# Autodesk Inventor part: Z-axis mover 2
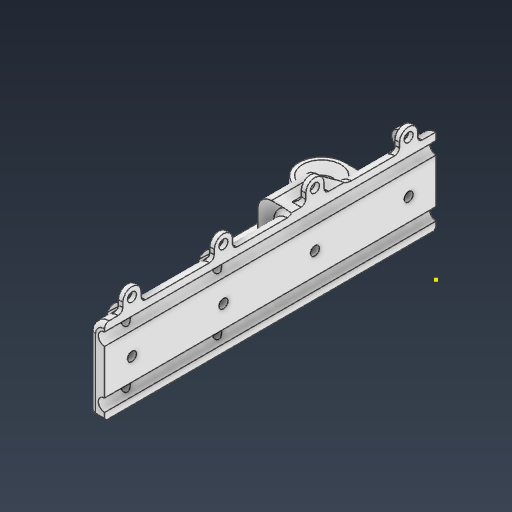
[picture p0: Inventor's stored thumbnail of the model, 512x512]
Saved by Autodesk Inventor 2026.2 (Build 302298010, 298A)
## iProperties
Created: 2026-04
Part Number: Z-axis mover 2
Material: ABS 플라스틱
Document SubType Name: Modeling
Designer: work
Density: 1.06 g/cm^3
Appearance: 매끄러움 - 흰색
Mass: 54.2435 g
Surface Area: 203.358 cm^2
Volume: 51.1731 cm^3
Author: work
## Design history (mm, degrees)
sketch "스케치1"
  geometry: L1 (0, 0)-(8, 0); L2 (0, 0)-(0, 8); L3 (0, 0)-(-8, 0); L4 (0, 0)-(0, -8); L5 (0, 0)-(50, 0); L6 (0, 0)-(-50, 0); L7 (0, 0)-(0, 50); L8 (25, 0)-(25, -380); L9 (-25, 0)-(-25, -380); L10 (-25, 0)-(-25, 70); L11 (25, -380)-(-25, -380); L12 (25, 0)-(25, 0); L13 (25, 0)-(25, 120); L14 (-37.5, -395)-(37.5, -395); L15 (37.5, -395)-(37.5, -365); L16 (37.5, -365)-(-37.5, -365); L17 (-37.5, -365)-(-37.5, -395); L18 (-37.5, -395)-(37.5, -365); L19 (37.5, -395)-(-37.5, -365); L20 (-62.5, 38)-(62.5, 38); L21 (62.5, 38)-(62.5, -38); L22 (62.5, -38)-(-62.5, -38); L23 (-62.5, -38)-(-62.5, 38); L24 (-62.5, 38)-(62.5, -38); L25 (62.5, 38)-(-62.5, -38); L26 (62.5, -25)-(-62.5, -25); L27 (17, 38)-(-17, 38); L28 (-17, 38)-(-17, 61); L29 (-17, 61)-(17, 61); L30 (17, 61)-(17, 38); L31 (-22, 60.236)-(-22, 100); L32 (-22, 100)-(-28, 100); L33 (-28, 100)-(-28, -380); L34 (-28, -380)-(-22, -380); L35 (-22, -380)-(-22, 100); L36 (-40, 38)-(40, 38); L37 (40, 38)-(40, 18); L38 (40, 18)-(-40, 18); L39 (-40, 18)-(-40, 38); C1 r 5.25 at (0, 0); C2 r 11.3 at (0, 0); C3 r 2 at (8, 0); C4 r 2 at (0, 8); C5 r 2 at (-8, 0); C6 r 2 at (0, -8); C7 r 4.4 at (50, 0); C8 r 4.4 at (-50, 0); C9 r 4 at (0, 50); 7 further points
  constraints: 78 end point, 12 midpoint, 10 parallel, 9 centre point, 9 coincident, 8 horizontal, 6 perpendicular, 6 point on line, 5 vertical, 2 symmetric about line, 1 collinear, 22 other
  dimensions: "d0" = 10.5 diameter of C1; "d1" = 22.6 diameter of C2; "d2" = 8 distance of L1.start L1.end; "d3" = 4 diameter of C3; "d6" = 360 deg dimension on C1.centre L1.end (derived); "d8" = 50 distance of L4.start L5.end; "d9" = 8.8 diameter of C7; "d10" = 50 distance of L4.start L7.end; "d11" = 8 diameter of C9; "d12" = 12 distance of point (0, 38) L7.end; "d15" = 450 distance of L9.end L10.end; "d16" = 25 distance from line of point (0, 0) L8; "d17" = 25 distance from line of L10 C1.centre; "d19" = 500 distance of L8.end L13.end; "d20" = 120 vertical distance of point (0, 0) L13.end; "d21" = 75 distance between parallel lines of L17 L15; "d22" = 30 distance of L14.end L15.end; "d23" = 125 distance between parallel lines of L23 L21; "d24" = 25 distance from line of point (0, 0) L26; "d25" = 340 distance between parallel lines of L16 L26 (derived); "d26" = 34 distance of L28.end L29.end; "d27" = 23 distance of L27.end L28.end; "d30" = 6 distance between parallel lines of L33 L35; "d31" = 80 distance of L37.end L38.end; "d32" = 20 distance of L36.end L37.end; "d60" = 30 distance of L10.end point (-25, 100)
  node "스케치 - 원형 패턴1" dims "d6" = 360 deg (derived)
extrude "돌출1" new body sketch "스케치1" distance "d33" = 6; taper "d34" = 0 deg
extrude "돌출2" join sketch "스케치1" distance "d35" = 4; taper "d36" = 0 deg
extrude "돌출3" join sketch "스케치1" distance "d37" = 38; taper "d38" = 0 deg
sketch "스케치2"
  geometry: L1 (102.5, 6)-(22.5, 6) reference; L2 (87.5, 6)-(87.5, 31); L3 (93.5, 6)-(93.5, 31); L4 (81.5, 31)-(81.5, 6); L5 (0, 0)-(125, 0) reference; L6 (62.5, 6)-(37.5, 6); L7 (37.5, 6)-(37.5, 31); L8 (37.5, 31)-(62.5, 31); L9 (62.5, 31)-(62.5, 6); L10 (30.5, 4)-(44.5, 4); L11 (44.5, 4)-(44.5, 18); L12 (44.5, 18)-(30.5, 18); L13 (30.5, 18)-(30.5, 4); L14 (30.5, 4)-(44.5, 18); L15 (44.5, 4)-(30.5, 18); L16 (44.5, -10.5)-(86.5, -10.5); L17 (86.5, -10.5)-(86.5, 32.5); L18 (86.5, 32.5)-(44.5, 32.5); L19 (44.5, 32.5)-(44.5, -10.5); L20 (44.5, -10.5)-(86.5, 32.5); L21 (86.5, -10.5)-(44.5, 32.5); L22 (47.5, 32.5)-(47.5, -10.5); L23 (37.5, 6)-(37.5, 31); L24 (43.5, 6)-(43.5, 31); L25 (31.5, 31)-(31.5, 6); L26 (47, 1.5)-(28, 1.5); L27 (28, 1.5)-(28, 20.5); L28 (28, 20.5)-(47, 20.5); L29 (47, 20.5)-(47, 1.5); L30 (47, 1.5)-(28, 20.5); L31 (28, 1.5)-(47, 20.5); C1 r 2.75 at (87.5, 6); C2 r 2.75 at (87.5, 31); C3 r 4.25 at (37.5, 31); A1 r 6 centre (87.5, 6) between (81.5, 6) and (93.5, 6); A2 r 6 centre (87.5, 31) between (93.5, 31) and (81.5, 31); A3 r 6 centre (37.5, 6) between (31.5, 6) and (43.5, 6); A4 r 6 centre (37.5, 31) between (43.5, 31) and (31.5, 31); 16 further points
  constraints: 62 end point, 11 midpoint, 10 parallel, 10 tangent, 8 point on circle, 7 centre point, 7 perpendicular, 5 point on line, 4 horizontal, 2 coincident
  dimensions: "d39" = 5.5 diameter of C1; "d40" = 25 distance of L2.start L6.start; "d41" = 25 distance of L2.start L2.end; "d42" = 5.5 diameter of C2; "d43" = 25 distance of L7.end L8.end; "d44" = 25 distance of L6.end L7.end; "d45" = 8.5 diameter of C3; "d46" = 14 distance of L11.end L12.end; "d47" = 14 distance of L10.end L11.end; "d48" = 43 distance of L16.end L17.end; "d50" = 20 distance of L7.end point (37.5, 11); "d51" = 39 distance between parallel lines of L17 L22; "d52" = 3 distance between parallel lines of L22 L19; "d59" = 2.5 distance between parallel lines of L28 L12
extrude "돌출4" join sketch "스케치2" distance "d53" = 145; taper "d54" = 0 deg
extrude "돌출5" cut sketch "스케치2" extent not by distance; stored distance "d55" = 10; taper "d56" = 0 deg
sketch "스케치3"
  geometry: L1 (-31.5, 20.5)-(-31.5, 31) reference; L2 (-43.5, 31)-(-43.5, 20.5) reference; L3 (-30.5, 4)-(-44.5, 4) reference; L4 (-44.5, 18)-(-30.5, 18) reference; L5 (-28, 20.5)-(-31.5, 20.5) reference; L6 (-43.5, 20.5)-(-47, 20.5) reference; L7 (-47, 1.5)-(-41.469, 1.5) reference; L8 (-33.531, 1.5)-(-28, 1.5) reference; L9 (-28, 1.5)-(-28, 20.5) reference; L10 (-30.5, 18)-(-30.5, 4) reference; L11 (-44.5, 4)-(-44.5, 18) reference; L12 (-47, 20.5)-(-47, 1.5) reference; C1 r 6 at (-37.5, 31); A1 r 6 centre (-37.5, 6) between (-41.469, 1.5) and (-33.531, 1.5) reference; A2 r 6 centre (-37.5, 31) between (-31.5, 31) and (-43.5, 31) reference; 5 further points
  constraints: 1 centre point, 1 concentric
extrude "돌출6" cut sketch "스케치3" stored distance "d57" = 145; taper "d58" = 0 deg
sketch "스케치5"
  geometry: L1 (29.25, 38)-(20.75, 38) reference; L2 (18, 38)-(32, 38) reference; L3 (32, 38)-(18, 38) reference; L4 (-25, 38)-(62.5, 38) reference; L5 (40, 38)-(62.5, 38) reference; L6 (-40, 38)-(40, 38) reference; L7 (-62.5, 38)-(-40, 38) reference; L8 (-62.5, 38)-(-25, 38) reference; L9 (-25, 38)-(-31, 38) reference; L10 (-31, 38)-(-19, 38) reference; L11 (-19, 38)-(-25, 38) reference; L12 (25, 38)-(25, 88); L13 (9.5, 103.5)-(40.5, 103.5); L14 (40.5, 103.5)-(40.5, 72.5); L15 (40.5, 72.5)-(9.5, 72.5); L16 (9.5, 72.5)-(9.5, 103.5); L17 (9.5, 103.5)-(40.5, 72.5); L18 (40.5, 103.5)-(9.5, 72.5); L19 (1.5, 111.5)-(48.5, 111.5); L20 (48.5, 111.5)-(48.5, 64.5); L21 (48.5, 64.5)-(1.5, 64.5); L22 (1.5, 64.5)-(1.5, 111.5); L23 (1.5, 111.5)-(48.5, 64.5); L24 (48.5, 111.5)-(1.5, 64.5); L25 (-22.25, 120)-(-22.25, -25) reference; L26 (-31, 38)-(-19, 38) reference; L27 (-31, 38)-(-31, 120) reference; L28 (-19, 120)-(-31, 120) reference; L29 (-19, 38)-(-19, 120) reference; L30 (62.5, 38)-(62.5, -25) reference; L31 (40, 18)-(40, 38) reference; L32 (-62.5, 38)-(-25, 38) reference; L33 (-62.5, -25)-(-62.5, 38) reference; L34 (62.5, -25)-(-62.5, -25) reference; L35 (62.5, 38)-(62.5, -25) reference; L36 (-25, 38)-(62.5, 38) reference; L37 (-19, 38)-(19, 38); L38 (19, 38)-(19, 62); L39 (19, 62)-(-19, 62); L40 (-19, 62)-(-19, 38); L41 (-19, 38)-(-19, 120) reference; C1 r 12.5 at (25, 88); C2 r 2 at (9.5, 72.5); C3 r 2 at (40.5, 103.5); C4 r 2 at (9.5, 103.5); C5 r 2 at (40.5, 72.5); C6 r 2 at (0, -8) reference; C7 r 2 at (8, 0) reference; C8 r 2 at (0, 8) reference; C9 r 2 at (-8, 0) reference; C10 r 5.25 at (0, 0) reference; C11 r 4.4 at (50, 0) reference; C12 r 4.4 at (-50, 0) reference; A1 r 28.971 centre (1.5, 140.471) between (-19, 120) and (1.5, 111.5); A2 r 15 centre (63.5, 64.5) between (48.5, 64.5) and (55.046, 52.109); A3 r 17.08 centre (45.42, 38) between (62.5, 38) and (55.046, 52.109); 15 further points
  constraints: 34 end point, 8 centre point, 6 parallel, 6 point on circle, 5 coincident, 5 midpoint, 4 perpendicular, 4 tangent, 3 horizontal, 2 point on line, 5 other
  dimensions: "d61" = 25 distance from line of point (0, 38) L12; "d62" = 25 diameter of C1; "d63" = 31 distance of L14.end L15.end; "d64" = 31 distance of L13.end L14.end; "d65" = 4 diameter of C2; "d66" = 4 diameter of C3; "d67" = 4 diameter of C4; "d68" = 4 diameter of C5; "d69" = 50 distance of L12.start L12.end; "d70" = 8 distance between parallel lines of L14 L20; "d71" = 15 radius of A2; "d73" = 24 distance of L39.end L37.start
extrude "돌출7" join sketch "스케치5" distance "d74" = 6; taper "d75" = 0 deg
sketch "스케치6"
  geometry: L1 (-81.5, 31)-(-81.5, 0) reference; L2 (-81.5, 0)-(-43.5, 0) reference; L3 (-43.5, 0)-(-43.5, 4) reference; L4 (-30.5, 6)-(-22.5, 6) reference; L5 (-44.5, 18)-(-44.5, 4) reference; L6 (-30.5, 18)-(-44.5, 18) reference; L7 (-30.5, 6)-(-30.5, 18) reference; L8 (-22.5, 6)-(-22.5, 38) reference; L9 (-102.5, 38)-(-22.5, 38) reference; L10 (-102.5, 6)-(-102.5, 38) reference; L11 (-125, 6)-(-102.5, 6) reference; L12 (-125, 0)-(-125, 6) reference; L13 (-125, 0)-(-93.5, 0) reference; L14 (-93.5, 0)-(-93.5, 31) reference; L15 (-81.5, 6)-(-81.5, 31) reference; L16 (-93.5, 31)-(-93.5, 0) reference; L17 (0, 0)-(-125, 0) reference; L18 (-93.5, 6)-(-81.5, 6); L19 (-81.5, 6)-(-81.5, 0); L20 (-81.5, 0)-(-93.5, 0); L21 (-93.5, 0)-(-93.5, 6); L22 (-81.5, 0)-(-93.5, 0) reference; L23 (-81.5, 0)-(-81.5, 6) reference; L24 (-90.25, 6)-(-84.75, 6) reference; L25 (-44.5, 4)-(-43.5, 4) reference; C1 r 4.25 at (-37.5, 31) reference; C2 r 2.75 at (-87.5, 31) reference; A1 r 6 centre (-87.5, 31) between (-81.5, 31) and (-93.5, 31) reference; A2 r 6 centre (-87.5, 31) between (-81.5, 31) and (-93.5, 31) reference; A3 r 2.75 centre (-87.5, 6) between (-84.75, 6) and (-90.25, 6) reference; 10 further points
  constraints: 8 end point, 2 parallel, 2 point on line, 1 horizontal, 1 perpendicular
extrude "돌출8" join sketch "스케치6" stored distance "d76" = 6; taper "d77" = 0 deg
sketch "스케치7"
  geometry: L1 (47, 6)-(81.5, 6) reference; L2 (47, 20.5)-(43.5, 20.5) reference; L3 (43.5, 20.5)-(43.5, 31) reference; L4 (31.5, 31)-(31.5, 20.5) reference; L5 (31.5, 20.5)-(28, 20.5) reference; L6 (28, 20.5)-(28, 6) reference; L7 (0, 6)-(28, 6) reference; L8 (0, 0)-(0, 6) reference; L9 (0, 0)-(125, 0) reference; L10 (125, 0)-(125, 6) reference; L11 (93.5, 6)-(125, 6) reference; L12 (93.5, 6)-(93.5, 31) reference; L13 (81.5, 31)-(81.5, 6) reference; L14 (44.5, 18)-(44.5, 4) reference; L15 (44.5, 4)-(30.5, 4) reference; L16 (30.5, 4)-(30.5, 18) reference; L17 (30.5, 18)-(44.5, 18) reference; L18 (43.5, 4)-(30.5, 4) reference; L19 (43.5, 4)-(43.5, 6) reference; L20 (30.5, 6)-(43.5, 6) reference; L21 (30.5, 4)-(30.5, 6) reference; L22 (81.5, 0)-(43.5, 0) reference; L23 (81.5, 0)-(81.5, 6) reference; L24 (43.5, 6)-(81.5, 6) reference; L25 (43.5, 0)-(43.5, 6) reference; L26 (47, 6)-(47, 20.5) reference; C1 r 2.75 at (87.5, 31) reference; C2 r 2.75 at (87.5, 6) reference; C3 r 2.75 at (87.5, 31) reference; A1 r 6 centre (37.5, 31) between (43.5, 31) and (31.5, 31) reference; A2 r 6 centre (87.5, 31) between (93.5, 31) and (81.5, 31) reference; 4 further points
extrude "돌출9" cut sketch "스케치7" extent not by distance; stored distance "d78" = 0; taper "d79" = 0 deg
sketch "스케치8"
  geometry: L1 (50.5, 10)-(74.5, 10); L2 (74.5, 10)-(74.5, 28); L3 (74.5, 28)-(50.5, 28); L4 (50.5, 28)-(50.5, 10); L5 (50.5, 10)-(74.5, 28); L6 (74.5, 10)-(50.5, 28); L7 (102.5, 38)-(22.5, 38) reference; L8 (62.5, 38)-(62.5, 0); C1 r 2 at (50.5, 28); C2 r 2 at (50.5, 10); C3 r 2 at (74.5, 10); C4 r 2 at (74.5, 28); 1 further point
  constraints: 14 end point, 4 centre point, 4 coincident, 4 midpoint, 2 parallel, 1 horizontal, 1 perpendicular, 1 vertical
  dimensions: "d80" = 24 distance of L3.end L2.end; "d81" = 18 distance of L2.end L1.end; "d82" = 4 diameter of C1; "d83" = 4 diameter of C2; "d84" = 4 diameter of C3; "d85" = 4 diameter of C4
extrude "돌출10" cut sketch "스케치8" extent not by distance; stored distance "d86" = 18 (derived); taper "d87" = 0 deg
sketch "스케치9"
  geometry: L1 (59, -32)-(59, -7) reference; L2 (71, -7)-(71, -32) reference; L3 (80, -32)-(71, -32) reference; L4 (80, -32)-(80, 0) reference; L5 (0, 0)-(80, 0) reference; L6 (0, -32)-(0, 0) reference; L7 (5.5, -32)-(0, -32) reference; L8 (5.5, -32)-(5.5, -17.5) reference; L9 (5.5, -17.5)-(9, -17.5) reference; L10 (9, -17.5)-(9, -7) reference; L11 (21, -7)-(21, -17.5) reference; L12 (21, -17.5)-(24.5, -17.5) reference; L13 (59, -32)-(24.5, -32) reference; L14 (24.5, -17.5)-(24.5, -32) reference; C1 r 2 at (28, -28) reference; C2 r 2 at (52, -28) reference; C3 r 2 at (28, -10) reference; C4 r 2 at (52, -10) reference; C5 r 2 at (52, -28) reference; A1 r 6 centre (65, -7) between (71, -7) and (59, -7) reference; A2 r 6 centre (15, -7) between (21, -7) and (9, -7) reference; 5 further points
  constraints: 4 coincident
hole "구멍1" sketch "스케치9" at (52, -10), (28, -10), (28, -28), (52, -28) diameter "d88" = 4; stored, may be unused: countersink angle "d92" = 90 deg, drill point angle "d94" = 0 deg; dims "d89" = 6, "d90" = 6.2, "d91" = 4, "d93" = 8
sketch "스케치10"
  geometry: L1 (32, -98.356)-(32, -111.5) reference; L2 (32, -111.5)-(48.5, -111.5) reference; L3 (48.5, -111.5)-(48.5, -64.5) reference; L4 (62.5, -38)-(62.5, 25) reference; L5 (62.5, 25)-(34.5, 25) reference; L6 (34.5, 25)-(34.5, -18) reference; L7 (34.5, -18)-(40, -18) reference; L8 (40, -18)-(40, -38) reference; L9 (32, -38)-(40, -38) reference; L10 (32, -38)-(32, -77.644) reference; L11 (-31, -18)-(-31, 25) reference; L12 (-31, 25)-(-62.5, 25) reference; L13 (-62.5, 25)-(-62.5, -38) reference; L14 (-62.5, -38)-(-40, -38) reference; L15 (-40, -38)-(-40, -18) reference; L16 (-40, -18)-(-31, -18) reference; L17 (-50, -10)-(-31, -10); L18 (-50, 10)-(-31, 10); L19 (50, 10)-(34.5, 10); L20 (50, -10)-(34.5, -10); C1 r 4.4 at (50, 0) reference; C2 r 2 at (40.5, -72.5) reference; C3 r 2 at (40.5, -103.5) reference; C4 r 4.4 at (-50, 0) reference; A1 r 15 centre (63.5, -64.5) between (55.046, -52.109) and (48.5, -64.5) reference; A2 r 17.08 centre (45.42, -38) between (55.046, -52.109) and (62.5, -38) reference; A3 r 12.5 centre (25, -88) between (32, -98.356) and (32, -77.644) reference; A4 r 10 centre (-50, 0) between (-50, -10) and (-50, 10); A5 r 10 centre (50, 0) between (50, 10) and (50, -10); 1 further point
  constraints: 8 end point, 4 perpendicular, 4 point on circle, 4 point on line, 4 tangent, 2 centre point, 2 coincident
  dimensions: "d95" = 20 diameter of A4; "d96" = 20 diameter of A5
extrude "돌출11" join sketch "스케치10" stored distance "d97" = 10; taper "d98" = 0 deg
fillet "모깎기1" dims "d99" = 6
sketch "스케치11"
  geometry: C1 r 4.25 at (0, 0) reference; 1 further point
extrude "돌출12" cut sketch "스케치11" extent not by distance; stored distance "d100" = 0; taper "d101" = 0 deg
fillet "모깎기2" dims "d102" = 2
fillet "모깎기3" dims "d103" = 0.5
chamfer "모따기1" distance "d104" = 1; stored, may be unused: second distance "d105" = 2, angle "d106" = 45 deg
sketch "스케치12"
  geometry: L1 (17.5, -61.936)-(17.5, -78) reference; L2 (17, -62)-(-17, -62) reference; L3 (-19, -60)-(-19, -118) reference; L4 (-21, -120)-(-19.813, -120) reference; L5 (1.5, -111.5)-(17.5, -111.5) reference; L6 (17.5, -98)-(17.5, -111.5) reference; L7 (42, -40)-(42, -17.621) reference; L8 (32.5, -78)-(32.5, -40) reference; L9 (32.5, -111.5)-(32.5, -98) reference; L10 (32.5, -111.5)-(42.5, -111.5) reference; L11 (48.5, -105.5)-(48.5, -64.5) reference; L12 (62.5, -38)-(62.5, 19) reference; L13 (56.5, 25)-(36.5, 25) reference; L14 (36.5, 16)-(36.5, 25) reference; L15 (50, 12)-(40.5, 12) reference; L16 (45.657, -12)-(50, -12) reference; L17 (42, -40)-(42, -17.621) reference; L18 (32.5, -40)-(42, -40) reference; C1 r 2 at (9.5, -72.5) reference; C2 r 2 at (9.5, -103.5) reference; C3 r 2 at (40.5, -103.5) reference; C4 r 2 at (40.5, -72.5) reference; C5 r 2 at (40.5, -103.5) reference; A1 r 2 centre (17, -60) between (17, -62) and (17.5, -61.936) reference; A2 r 2 centre (-17, -60) between (-19, -60) and (-17, -62) reference; A3 r 2 centre (-21, -118) between (-21, -120) and (-19, -118) reference; A4 r 2 centre (-19.813, -118) between (-19.813, -120) and (-18.437, -119.451) reference; A5 r 28.971 centre (1.5, -140.471) between (1.5, -111.5) and (-18.437, -119.451) reference; A6 r 12.5 centre (25, -88) between (17.5, -78) and (17.5, -98) reference; A7 r 12.5 centre (25, -88) between (32.5, -98) and (32.5, -78) reference; A8 r 6 centre (42.5, -105.5) between (42.5, -111.5) and (48.5, -105.5) reference; A9 r 15 centre (63.5, -64.5) between (55.046, -52.109) and (48.5, -64.5) reference; A10 r 17.08 centre (45.42, -38) between (55.046, -52.109) and (62.5, -38) reference; A11 r 6 centre (56.5, 19) between (62.5, 19) and (56.5, 25) reference; A12 r 4 centre (40.5, 16) between (36.5, 16) and (40.5, 12) reference; A13 r 12 centre (50, 0) between (50, -12) and (50, 12) reference; A14 r 4 centre (45.657, -16) between (45.657, -12) and (42, -17.621) reference; 5 further points
  constraints: 4 coincident
hole "구멍2" sketch "스케치12" at (9.5, -103.5), (40.5, -103.5), (40.5, -72.5), (9.5, -72.5) diameter "d107" = 4; stored, may be unused: countersink angle "d111" = 90 deg, drill point angle "d113" = 0 deg; dims "d108" = 6, "d109" = 6.2, "d110" = 4, "d112" = 8
fillet "모깎기4" dims "d114" = 10
sketch "스케치13"
  geometry: L1 (78, -30)-(0, -30) reference; L2 (78, 0)-(78, -30) reference; L3 (0, 0)-(78, 0) reference; L4 (0, -30)-(0, 0) reference; L5 (68, 0)-(28, 0); L6 (28, 0)-(28, -25); L7 (28, -25)-(68, -25); L8 (68, -25)-(68, 0); C1 r 4 at (28, 0); C2 r 4 at (28, -25); C3 r 4 at (68, -25); C4 r 4 at (68, 0); 1 further point
  constraints: 8 end point, 4 centre point, 2 parallel, 1 coincident, 1 horizontal, 1 perpendicular, 1 point on line
  dimensions: "d115" = 40 distance of L7.end L6.end; "d116" = 25 distance of L6.end L5.end; "d117" = 10 distance between parallel lines of L2 L8; "d118" = 8 diameter of C1; "d119" = 8 diameter of C2; "d120" = 8 diameter of C3; "d121" = 8 diameter of C4
  node "투영된 루프17"
extrude "돌출13" join sketch "스케치13" stored distance "d122" = 8 (derived); taper "d123" = 0 deg
extrude "돌출14" join sketch "스케치13" distance "d124" = 1.5; taper "d125" = 0 deg
sketch "스케치14"
  geometry: L1 (4, 0)-(36, 0) reference; L2 (-28, 0)-(-4, 0) reference; L3 (-28, -30)-(-28, 0) reference; L4 (50, -30)-(-28, -30) reference; L5 (50, 0)-(50, -30) reference; L6 (44, 0)-(50, 0) reference; C1 r 4 at (40, -25) reference; C2 r 4 at (0, -25) reference; C3 r 2 at (0, 0); C4 r 2 at (0, -25); C5 r 2 at (40, -25); C6 r 2 at (40, 0); A1 r 4 centre (40, 0) between (36, 0) and (44, 0) reference; A2 r 4 centre (0, 0) between (-4, 0) and (4, 0) reference; 1 further point
  constraints: 4 centre point, 4 coincident
  dimensions: "d126" = 4 diameter of C3; "d127" = 4 diameter of C4; "d128" = 4 diameter of C5; "d129" = 4 diameter of C6
  node "투영된 루프18"
extrude "돌출15" cut sketch "스케치14" stored distance "d130" = 1.5; taper "d131" = 0 deg
extrude "돌출16" cut sketch "스케치14" stored distance "d132" = 10; taper "d133" = 0 deg
fillet "모깎기5" dims "d134" = 2
sketch "스케치15"
  geometry: L1 (-21.127, -38)-(34, -38) reference; L2 (25, -38)-(25, -18); C1 r 2 at (25, -18); C2 r 2 at (25, -30); 1 further point
  constraints: 2 centre point, 2 end point, 2 point on line, 1 coincident, 1 vertical
  dimensions: "d135" = 20 distance of L2.start L2.end; "d136" = 25 distance from line of L2 point (0, 0); "d137" = 4 diameter of C1; "d138" = 4 diameter of C2; "d139" = 12 distance of L2.end C2.centre
extrude "돌출17" cut sketch "스케치15" stored distance "d140" = 10; taper "d141" = 0 deg; dims "d39" = 5.5, "d40" = 25, "d41" = 25, "d42" = 5.5, "d43" = 25, "d44" = 25, "d45" = 8.5, "d46" = 14, "d47" = 14, "d48" = 43, "d50" = 20, "d51" = 39, "d52" = 3, "d59" = 2.5
sketch "스케치16" dims "d145" = 7
  geometry: L1 (13, -21.5)-(13, -1.9); L2 (8, -25)-(31.5, -25) reference; L3 (6, -23)-(6, 0) reference; L4 (13, -5.4)-(6, -5.4); L5 (13, 1.6)-(5.783, 1.6); L6 (13, -18)-(6, -18); L7 (-42.5, -26.5)-(-42.5, -13.5) reference; L8 (-56.5, -27.5)-(-43.5, -27.5) reference; L9 (-57.5, -13.5)-(-57.5, -26.5) reference; L10 (-43.5, -12.5)-(-56.5, -12.5) reference; L11 (31.5, -30)-(-81.5, -30) reference; L12 (31.5, -25)-(31.5, -30) reference; L13 (8, -25)-(31.5, -25) reference; L14 (6, -23)-(6, 0) reference; L15 (-6, 0)-(-6, -23) reference; L16 (-38.5, -25)-(-8, -25) reference; L17 (-40.5, -23)-(-40.5, -12.5) reference; L18 (-42.5, -10.5)-(-44, -10.5) reference; L19 (-44, -10.5)-(-44, 0) reference; L20 (-56, 0)-(-56, -10.5) reference; L21 (-56, -10.5)-(-57.5, -10.5) reference; L22 (-59.5, -12.5)-(-59.5, -23) reference; L23 (-81.5, -25)-(-61.5, -25) reference; L24 (-81.5, -30)-(-81.5, -25) reference; C1 r 2 at (13, -21.5); C2 r 2 at (13, -1.9); C3 r 4.25 at (-50, 0) reference; C4 r 2.75 at (0, 0) reference; C5 r 2.75 at (0, -25) reference; A1 r 3.5 centre (13, -1.9) between (13, -5.4) and (13, 1.6); A2 r 6 centre (0, 0) between (6, 0) and (-6, 0) reference; A3 r 1 centre (-43.5, -13.5) between (-42.5, -13.5) and (-43.5, -12.5) reference; A4 r 1 centre (-43.5, -26.5) between (-43.5, -27.5) and (-42.5, -26.5) reference; A5 r 1 centre (-56.5, -26.5) between (-57.5, -26.5) and (-56.5, -27.5) reference; A6 r 1 centre (-56.5, -13.5) between (-56.5, -12.5) and (-57.5, -13.5) reference; A7 r 2 centre (8, -23) between (6, -23) and (8, -25) reference; A8 r 6 centre (0, 0) between (6, 0) and (-6, 0) reference; A9 r 2 centre (-8, -23) between (-8, -25) and (-6, -23) reference; A10 r 2 centre (-38.5, -23) between (-40.5, -23) and (-38.5, -25) reference; A11 r 2 centre (-42.5, -12.5) between (-40.5, -12.5) and (-42.5, -10.5) reference; A12 r 6 centre (-50, 0) between (-44, 0) and (-56, 0) reference; A13 r 2 centre (-57.5, -12.5) between (-57.5, -10.5) and (-59.5, -12.5) reference; A14 r 2 centre (-61.5, -23) between (-61.5, -25) and (-59.5, -23) reference; 5 further points
  constraints: 8 end point, 4 point on line, 3 centre point, 3 coincident, 3 perpendicular, 3 point on circle, 2 horizontal, 1 tangent, 1 vertical, 3 other
  dimensions: "d142" = 4 diameter of C1; "d143" = 4 diameter of C2; "d144" = 7 diameter of A1; "d146" = 19.6 distance of L1.start L1.end; "d147" = 7 distance from line of L3 L1.start
extrude "돌출18" join sketch "스케치16" distance "d148" = 3; taper "d149" = 0 deg
fillet "모깎기6" dims "d150" = 1
sketch "스케치17"
  geometry: L1 (0, 0)-(0, 25); L2 (13.5, 25)-(-17, 25) reference; L3 (7.5, 21)-(-7.5, 21); L4 (58.5, -34)-(58.5, -19); L5 (62.5, -38)-(62.5, 19) reference; C1 r 2 at (-7.5, 21); C2 r 2 at (7.5, 21); C3 r 2 at (58.5, -34); C4 r 2 at (58.5, -19); 1 further point
  constraints: 6 end point, 4 centre point, 4 coincident, 2 point on line, 2 vertical, 1 horizontal, 1 midpoint
  dimensions: "d151" = 15 distance of L3.start L3.end; "d152" = 4 diameter of C1; "d153" = 4 diameter of C2; "d154" = 4 distance between parallel lines of L2 L3; "d155" = 15 distance of L4.start L4.end; "d156" = 4 diameter of C3; "d157" = 4 diameter of C4; "d158" = 4 distance between parallel lines of L5 L4; "d159" = 4 horizontal distance of L5.start L4.start
extrude "돌출19" cut sketch "스케치17" extent not by distance; stored distance "d160" = 0; taper "d161" = 0 deg
sketch "스케치18"
  geometry: L1 (-42, -17.621)-(-42, -38) reference; L2 (-50, -12)-(-45.657, -12) reference; C1 r 16 at (-60, -30); 1 further point
  constraints: 1 centre point
  dimensions: "d162" = 32 diameter of C1; "d163" = 2 distance edge to line of C1 L1; "d164" = 2 distance edge to line of C1 L2
extrude "돌출20" cut sketch "스케치18" distance "d165" = 2; taper "d166" = 0 deg
sketch "스케치19"
  geometry: L1 (56.5, 19)-(42.5, 19); L2 (56.5, 23)-(42.5, 23); L3 (42.5, 15)-(56.5, 15); L4 (36.5, 16)-(36.5, 25) reference; L5 (-56.5, 19)-(-48, 19); L6 (-56.5, 15)-(-48, 15); L7 (-48, 23)-(-56.5, 23); L8 (-46.144, -38)-(-42, -38) reference; L9 (-42, -17.621)-(-42, -38) reference; L10 (-50, -12)-(-45.657, -12) reference; L11 (-37, 12)-(-50, 12) reference; L12 (-33, 21)-(-33, 16) reference; L13 (-41.742, 21)-(-33, 21) reference; L14 (-41.742, 25)-(-56.5, 25) reference; L15 (-62.5, 19)-(-62.5, -14.197) reference; L16 (36.5, -52)-(44.5, -52); L17 (44.5, -52)-(44.5, -44); L18 (44.5, -44)-(36.5, -44); L19 (36.5, -44)-(36.5, -52); L20 (32.5, -40)-(42, -40) reference; L21 (32.5, -78)-(32.5, -40) reference; L22 (13.5, 25)-(13.5, -16.011) reference; L23 (13.5, 25)-(-17, 25) reference; L24 (-17, -12)-(-17, 25) reference; L25 (9.631, -16)-(-9.631, -16) reference; L26 (32.5, -78)-(32.5, -40) reference; L27 (32.5, -111.5)-(32.5, -98) reference; L28 (32.5, -111.5)-(42.5, -111.5) reference; L29 (48.5, -105.5)-(48.5, -64.5) reference; L30 (62.5, -38)-(62.5, 19) reference; L31 (56.5, 25)-(36.5, 25) reference; L32 (36.5, 16)-(36.5, 25) reference; L33 (50, 12)-(40.5, 12) reference; L34 (45.657, -12)-(50, -12) reference; L35 (42, -40)-(42, -17.621) reference; L36 (32.5, -40)-(42, -40) reference; L37 (-41.742, 25)-(-41.742, 21) reference; C1 r 1.5 at (36.5, -52); C2 r 1.5 at (36.5, -44); C3 r 1.5 at (44.5, -44); C4 r 1.5 at (44.5, -52); A1 r 4 centre (56.5, 19) between (56.5, 15) and (56.5, 23); A2 r 4 centre (42.5, 19) between (42.5, 23) and (42.5, 15); A3 r 6 centre (56.5, 19) between (62.5, 19) and (56.5, 25) reference; A4 r 4 centre (-56.5, 19) between (-56.5, 23) and (-56.5, 15); A5 r 4 centre (-48, 19) between (-48, 15) and (-48, 23); A6 r 6 centre (-56.5, 19) between (-56.5, 25) and (-62.5, 19) reference; A7 r 16 centre (-60, -30) between (-46.144, -38) and (-62.5, -14.197) reference; A8 r 4 centre (-45.657, -16) between (-42, -17.621) and (-45.657, -12) reference; A9 r 12 centre (-50, 0) between (-50, 12) and (-50, -12) reference; A10 r 4 centre (-37, 16) between (-37, 12) and (-33, 16) reference; A11 r 6 centre (-56.5, 19) between (-56.5, 25) and (-62.5, 19) reference; A12 r 4 centre (-13, -12) between (-17, -12) and (-13.912, -15.895) reference; A13 r 12.5 centre (25, -88) between (32.5, -98) and (32.5, -78) reference; A14 r 6 centre (42.5, -105.5) between (42.5, -111.5) and (48.5, -105.5) reference; A15 r 15 centre (63.5, -64.5) between (55.046, -52.109) and (48.5, -64.5) reference; A16 r 17.08 centre (45.42, -38) between (55.046, -52.109) and (62.5, -38) reference; A17 r 6 centre (56.5, 19) between (62.5, 19) and (56.5, 25) reference; A18 r 4 centre (40.5, 16) between (36.5, 16) and (40.5, 12) reference; A19 r 12 centre (50, 0) between (50, -12) and (50, 12) reference; A20 r 4 centre (45.657, -16) between (45.657, -12) and (42, -17.621) reference; 8 further points
  constraints: 24 end point, 10 point on circle, 8 centre point, 8 tangent, 4 coincident, 4 parallel, 3 horizontal, 3 midpoint, 2 concentric, 1 perpendicular, 4 other
  dimensions: "d167" = 8 diameter of A2; "d168" = 2 distance from line of point (38.5, 19) L4; "d169" = 8 diameter of A5; "d171" = 3 diameter of C1; "d172" = 3 diameter of C2; "d173" = 3 diameter of C3; "d174" = 3 diameter of C4; "d175" = 8 distance of L16.end L17.end; "d176" = 8 distance of L17.end L18.end; "d177" = 4 distance between parallel lines of L20 L18; "d178" = 4 distance from line of L21 point (36.5, -48)
extrude "돌출21" cut sketch "스케치19" extent not by distance; stored distance "d179" = 0; taper "d180" = 0 deg
sketch "스케치20"
  geometry: 1 further point
sketch "스케치21"
  geometry: L1 (7.5, -26.5)-(7.5, -13.5) reference; L2 (-6.5, -27.5)-(6.5, -27.5) reference; L3 (-7.5, -13.5)-(-7.5, -26.5) reference; L4 (6.5, -12.5)-(-6.5, -12.5) reference; L5 (81.5, -30)-(-31.5, -30) reference; L6 (81.5, -25)-(81.5, -30) reference; L7 (66.742, -25)-(81.5, -25) reference; L8 (63, -18)-(57, -18) reference; L9 (56, -17)-(56, -6.4) reference; L10 (57, -5.4)-(63, -5.4) reference; L11 (63, 1.6)-(56.499, 1.6) reference; L12 (44, 0)-(44, -23) reference; L13 (11.5, -25)-(42, -25) reference; L14 (9.5, -23)-(9.5, -12.5) reference; L15 (7.5, -10.5)-(6, -10.5) reference; L16 (6, -10.5)-(6, 0) reference; L17 (-6, 0)-(-6, -10.5) reference; L18 (-6, -10.5)-(-7.5, -10.5) reference; L19 (-9.5, -12.5)-(-9.5, -23) reference; L20 (-31.5, -25)-(-11.5, -25) reference; L21 (-31.5, -30)-(-31.5, -25) reference; L22 (-9.5, -12.5)-(-9.5, -7.5); L23 (-7.5, -5.5)-(7.5, -5.5); L24 (9.5, -12.5)-(9.5, -7.5); L25 (7.5, -13.5)-(7.5, -7.5); L26 (7.5, -7.5)-(-7.5, -7.5); L27 (-7.5, -7.5)-(-7.5, -13.5); L28 (-9.5, -13.5)-(9.5, -13.5); C1 r 2 at (63, -1.9) reference; C2 r 2 at (63, -21.5) reference; C3 r 4.25 at (0, 0) reference; C4 r 2.75 at (50, 0) reference; C5 r 2.75 at (50, -25) reference; A1 r 1 centre (6.5, -13.5) between (7.5, -13.5) and (6.5, -12.5) reference; A2 r 1 centre (6.5, -26.5) between (6.5, -27.5) and (7.5, -26.5) reference; A3 r 1 centre (-6.5, -26.5) between (-7.5, -26.5) and (-6.5, -27.5) reference; A4 r 1 centre (-6.5, -13.5) between (-6.5, -12.5) and (-7.5, -13.5) reference; A5 r 1 centre (66.742, -24) between (65.91, -23.444) and (66.742, -25) reference; A6 r 3.5 centre (63, -21.5) between (65.91, -23.444) and (63, -18) reference; A7 r 1 centre (57, -17) between (56, -17) and (57, -18) reference; A8 r 1 centre (57, -6.4) between (57, -5.4) and (56, -6.4) reference; A9 r 3.5 centre (63, -1.9) between (63, -5.4) and (63, 1.6) reference; A10 r 1 centre (56.499, 2.6) between (55.571, 2.229) and (56.499, 1.6) reference; A11 r 6 centre (50, 0) between (55.571, 2.229) and (44, 0) reference; A12 r 2 centre (42, -23) between (42, -25) and (44, -23) reference; A13 r 2 centre (11.5, -23) between (9.5, -23) and (11.5, -25) reference; A14 r 2 centre (7.5, -12.5) between (9.5, -12.5) and (7.5, -10.5) reference; A15 r 6 centre (0, 0) between (6, 0) and (-6, 0) reference; A16 r 2 centre (-7.5, -12.5) between (-7.5, -10.5) and (-9.5, -12.5) reference; A17 r 2 centre (-11.5, -23) between (-11.5, -25) and (-9.5, -23) reference; A18 r 2 centre (-7.5, -7.5) between (-7.5, -5.5) and (-9.5, -7.5); A19 r 2 centre (7.5, -7.5) between (9.5, -7.5) and (7.5, -5.5); A20 r 2 centre (-5.5, -9.5) between (-5.5, -7.5) and (-7.5, -9.5); A21 r 2 centre (5.5, -9.5) between (7.5, -9.5) and (5.5, -7.5); 8 further points
  constraints: 14 end point, 8 point on circle, 8 tangent, 6 point on line, 4 centre point, 2 vertical, 1 horizontal, 1 midpoint, 1 perpendicular, 12 other
  dimensions: "d181" = 7 distance from line of L4 point (0, -5.5); "d182" = 2 radius of A19; "d183" = 2 radius of A18; "d184" = 2 radius of A20; "d185" = 2 radius of A21; "d186" = 1 distance between parallel lines of L4 L28
  node "투영된 루프21"
extrude "돌출22" join sketch "스케치21" stored distance "d187" = 10; taper "d188" = 0 deg
extrude "돌출23" cut sketch "스케치21" extent not by distance; stored distance "d189" = 10; taper "d190" = 0 deg
chamfer "모따기2" distance "d191" = 0.5; stored, may be unused: second distance "d192" = 2, angle "d193" = 45 deg
node "작업 평면1"
sketch "스케치22"
  geometry: L1 (-37, 16.5)-(0, 16.5) reference; L2 (5.97, 17.5)-(26, 17.5) reference; L3 (28, 16.5)-(106, 16.5) reference; L4 (96, 12.5)-(96, 20.5); L5 (100, 12.5)-(100, 20.5); L6 (92, 20.5)-(92, 12.5); L7 (108, 13.25)-(108, 7.75) reference; L8 (52, 20.5)-(52, 12.5); L9 (60, 12.5)-(60, 20.5); L10 (56, 12.5)-(56, 20.5); L11 (11.985, 21.8)-(11.985, 14.348); L12 (19.985, 11.991)-(19.985, 21.8); L13 (15.985, 13.2)-(15.985, 21.8); L14 (-29, 20.5)-(-29, 12.5); L15 (-21, 12.5)-(-21, 20.5); L16 (-25, 12.5)-(-25, 20.5); L17 (-29, 14.5)-(-21, 14.5); L18 (11.985, 15.5)-(19.985, 15.5); L19 (52, 14.5)-(60, 14.5); L20 (92, 14.5)-(100, 14.5); C1 r 2 at (96, 20.5); C2 r 2 at (56, 20.5); C3 r 2 at (15.985, 21.8); C4 r 2 at (-25, 20.5); A1 r 4 centre (96, 12.5) between (92, 12.5) and (100, 12.5); A2 r 4 centre (96, 20.5) between (100, 20.5) and (92, 20.5); A3 r 4 centre (56, 20.5) between (60, 20.5) and (52, 20.5); A4 r 4 centre (15.985, 21.8) between (19.985, 21.8) and (11.985, 21.8); A5 r 4 centre (-25, 20.5) between (-21, 20.5) and (-29, 20.5); 7 further points
  constraints: 40 end point, 15 point on line, 10 point on circle, 10 tangent, 9 centre point, 7 perpendicular, 5 midpoint, 4 coincident, 4 parallel, 2 other
  dimensions: "d194" = 4 distance of point (96, 16.5) L4.end; "d195" = 8 diameter of A2; "d196" = 4 diameter of C1; "d197" = 12 distance between parallel lines of L7 L4; "d198" = 8 diameter of A3; "d199" = 4 diameter of C2; "d200" = 8 diameter of A4; "d201" = 4 diameter of C3; "d202" = 8 diameter of A5; "d203" = 4 diameter of C4; "d204" = 40 distance between parallel lines of L4 L10; "d205" = 12 distance of L1.start point (-25, 16.5); "d206" = 2 distance between parallel lines of L20 L3; "d207" = 2 distance between parallel lines of L18 L2
extrude "돌출24" join sketch "스케치22" stored distance "d208" = 4; taper "d209" = 0 deg
sketch "스케치23"
  geometry: L1 (68, 30)-(68, 5); L2 (0, 30)-(78, 30) reference; L3 (28, 30)-(28, 5); L4 (80, 7.75)-(-65, 7.75) reference; L5 (68, 17.5)-(-65, 17.5); L6 (-65, 30)-(-65, 7) reference; L7 (-53, 40)-(-53, -1); L8 (-8.015, 37)-(-16.015, 37) reference; L9 (-8.015, 37)-(-8.015, 41.3) reference; L10 (-16.015, 41.3)-(-16.015, 37) reference; L11 (-12.015, 41.3)-(-12.015, -1); L12 (-2, -1)-(-59, -1) reference; C1 r 2 at (28, 30) reference; C2 r 2 at (68, 30) reference; C3 r 2 at (68, 5) reference; C4 r 2 at (28, 5) reference; C5 r 2 at (-53, 40) reference; C6 r 2 at (-53, 17.5); C7 r 2 at (28, 17.5); C8 r 2 at (68, 17.5); C9 r 2 at (-12.015, 41.3) reference; C10 r 2 at (-12.015, 17.5); A1 r 4 centre (-12.015, 41.3) between (-8.015, 41.3) and (-16.015, 41.3) reference; 2 further points
  constraints: 10 end point, 7 point on line, 4 centre point, 3 perpendicular, 2 coincident, 2 midpoint, 1 vertical
  dimensions: "d210" = 4 diameter of C6; "d211" = 4 diameter of C7; "d212" = 4 diameter of C8; "d213" = 4 diameter of C10
extrude "돌출25" cut sketch "스케치23" distance "d214" = 34; taper "d216" = 0 deg; dims "d215" = 20, "d217" = 0
sketch "스케치24"
  geometry: C1 r 2 at (28, 17.5) reference; 2 further points
  constraints: 1 coincident
hole "구멍3" sketch "스케치24" at (28, 17.5) diameter "d218" = 4; stored, may be unused: countersink angle "d222" = 90 deg, drill point angle "d224" = 118 deg; dims "d219" = 6, "d220" = 6.2, "d221" = 3, "d223" = 8
sketch "스케치25"
  geometry: C1 r 2 at (68, 17.5) reference; 2 further points
  constraints: 1 coincident
hole "구멍4" sketch "스케치25" at (68, 17.5) diameter "d225" = 4; stored, may be unused: countersink angle "d229" = 90 deg, drill point angle "d231" = 118 deg; dims "d226" = 6, "d227" = 6.2, "d228" = 3, "d230" = 8
sketch "스케치26"
  geometry: C1 r 2 at (-25, -2) reference; C2 r 3.1 at (-25, -2); 1 further point
  constraints: 1 centre point, 1 coincident
  dimensions: "d232" = 6.2 diameter of C2
extrude "돌출26" cut sketch "스케치26" distance "d233" = 34; taper "d235" = 0 deg; dims "d234" = 3, "d236" = 0
sketch "스케치27"
  geometry: L1 (20, -12.5)-(0, -12.5) reference; L2 (20, -12.5)-(20, 11.5) reference; L3 (0, 11.5)-(20, 11.5) reference; L4 (0, 0)-(0, 11.5) reference; L5 (0, -12.5)-(0, 0) reference; C1 r 2 at (9.985, -2) reference; C2 r 3.1 at (9.985, -2); 1 further point
  constraints: 1 centre point, 1 coincident
  dimensions: "d237" = 6.2 diameter of C2
extrude "돌출27" cut sketch "스케치27" distance "d238" = 3; taper "d239" = 0 deg
sketch "스케치28"
  geometry: L1 (-53.47, 16)-(-58, 16) reference; L2 (0, 16)-(-53.47, 16) reference; L3 (0, 16)-(0, 0) reference; L4 (20, 0)-(0, 0) reference; L5 (20, 31)-(20, 0) reference; L6 (20, 31)-(-58, 31) reference; L7 (-58, 16)-(-58, 31) reference; C1 r 2 at (-8, 18.5) reference; C2 r 2 at (-48, 18.5) reference; C3 r 6 at (-48, 18.5); C4 r 6 at (-8, 18.5); 1 further point
  constraints: 2 centre point, 2 coincident
  dimensions: "d240" = 12 diameter of C3; "d241" = 12 diameter of C4
extrude "돌출28" cut sketch "스케치28" extent not by distance; stored distance "d242" = 0; taper "d243" = 0 deg
sketch "스케치29"
  geometry: L1 (-144.725, 76.024)-(196.362, 76.024); L2 (196.362, 76.024)-(196.362, -88.872); L3 (196.362, -88.872)-(-144.725, -88.872); L4 (-144.725, -88.872)-(-144.725, 76.024); 1 further point
  constraints: 8 end point, 2 parallel, 1 horizontal, 1 perpendicular
fillet "모깎기7" dims "d244" = 2
extrude "돌출29" cut sketch "스케치29" extent not by distance; stored distance "d245" = 0; taper "d246" = 0 deg
chamfer "모따기3" distance "d247" = 4; stored, may be unused: second distance "d248" = 2, angle "d249" = 45 deg
sketch "스케치30"
  geometry: C1 r 4.4 at (0, 0) reference; C2 r 5 at (0, 0); 1 further point
  constraints: 1 centre point, 1 coincident
  dimensions: "d250" = 10 diameter of C2
extrude "돌출30" cut sketch "스케치30" extent not by distance; stored distance "d251" = 0; taper "d252" = 0 deg
node "솔리드1"
node "투영된 루프1"
node "투영된 루프2"
node "투영된 루프3"
node "투영된 루프4"
node "투영된 루프5"
node "투영된 루프6"
node "투영된 루프7"
node "투영된 루프8"
node "투영된 루프9"
node "투영된 루프10"
node "투영된 루프11"
node "투영된 루프12"
node "투영된 루프13"
node "투영된 루프14"
node "투영된 루프15"
node "투영된 루프16"
node "투영된 루프19"
node "투영된 루프20"
node "투영된 루프22"
node "투영된 루프23"
node "투영된 루프24"
feature "A9D066F2-1C7D-4E18-AEED-F7BC21143FA4" dims "d88" = 4, "d89" = 6, "d90" = 6.2, "d91" = 4, "d92" = 90 deg, "d93" = 8, "d94" = 0
